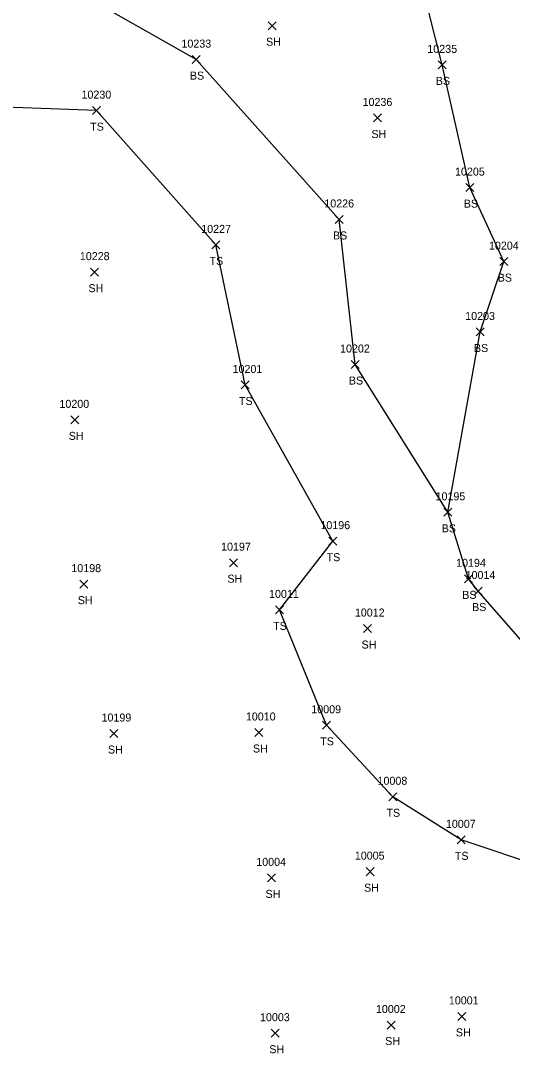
# Model space of a CAD drawing. Extents: x 1475671 to 1477951, y 592661 to 593821.
# Drawn here: x 1476720.5 to 1476843.4, y 592698.9 to 592957 of the extents above; entities that cross this region are included whole.
import ezdxf

# ---------------------------------------------------------------- set-up
doc = ezdxf.new("R2010")
doc.units = 0
for name, color, linetype in [('L_A', 7, 'Continuous'), ('L_I', 7, 'Continuous'), ('L_TIC', 7, 'Continuous'), ('LELB', 7, 'Continuous')]:
    doc.layers.add(name, color=color, linetype=linetype)

msp = doc.modelspace()

# ---------------------------------------------------------------- linework, layer by layer
at = {"layer": 'L_TIC'}
for points in [[(1476782.31, 592954.69), (1476784.31, 592956.69)], [(1476784.31, 592954.69), (1476782.31, 592956.69)], [(1476763.33, 592946.22), (1476765.33, 592948.22)], [(1476765.33, 592946.22), (1476763.33, 592948.22)], [(1476824.78, 592944.91), (1476826.78, 592946.91)], [(1476826.78, 592944.91), (1476824.78, 592946.91)], [(1476738.44, 592933.48), (1476740.44, 592935.48)], [(1476740.44, 592933.48), (1476738.44, 592935.48)], [(1476808.65, 592931.64), (1476810.65, 592933.64)], [(1476810.65, 592931.64), (1476808.65, 592933.64)], [(1476831.77, 592914.24), (1476833.77, 592916.24)], [(1476833.77, 592914.24), (1476831.77, 592916.24)], [(1476799.09, 592906.29), (1476801.09, 592908.29)], [(1476801.09, 592906.29), (1476799.09, 592908.29)], [(1476768.27, 592899.93), (1476770.27, 592901.93)], [(1476770.27, 592899.93), (1476768.27, 592901.93)], [(1476840.26, 592895.75), (1476842.26, 592897.75)], [(1476842.26, 592895.75), (1476840.26, 592897.75)], [(1476737.94, 592893.12), (1476739.94, 592895.12)], [(1476739.94, 592893.12), (1476737.94, 592895.12)], [(1476834.32, 592878.17), (1476836.32, 592880.17)], [(1476836.32, 592878.17), (1476834.32, 592880.17)], [(1476803.05, 592870.04), (1476805.05, 592872.04)], [(1476805.05, 592870.04), (1476803.05, 592872.04)], [(1476775.62, 592864.94), (1476777.62, 592866.94)], [(1476777.62, 592864.94), (1476775.62, 592866.94)], [(1476733, 592856.22), (1476735, 592858.22)], [(1476735, 592856.22), (1476733, 592858.22)], [(1476826.26, 592833.12), (1476828.26, 592835.12)], [(1476828.26, 592833.12), (1476826.26, 592835.12)], [(1476826.26, 592833.12), (1476828.26, 592835.12)], [(1476828.26, 592833.12), (1476826.26, 592835.12)], [(1476797.53, 592825.91), (1476799.53, 592827.91)], [(1476799.53, 592825.91), (1476797.53, 592827.91)], [(1476772.67, 592820.53), (1476774.67, 592822.53)], [(1476774.67, 592820.53), (1476772.67, 592822.53)], [(1476735.25, 592815.17), (1476737.25, 592817.17)], [(1476737.25, 592815.17), (1476735.25, 592817.17)], [(1476831.4, 592816.5), (1476833.4, 592818.5)], [(1476833.4, 592816.5), (1476831.4, 592818.5)], [(1476833.85, 592813.45), (1476835.85, 592815.45)], [(1476835.85, 592813.45), (1476833.85, 592815.45)], [(1476784.16, 592808.74), (1476786.16, 592810.74)], [(1476786.16, 592808.74), (1476784.16, 592810.74)], [(1476806.18, 592804.08), (1476808.18, 592806.08)], [(1476808.18, 592804.08), (1476806.18, 592806.08)], [(1476779.03, 592778.11), (1476781.03, 592780.11)], [(1476781.03, 592778.11), (1476779.03, 592780.11)], [(1476795.94, 592779.91), (1476797.94, 592781.91)], [(1476797.94, 592779.91), (1476795.94, 592781.91)], [(1476742.8, 592777.85), (1476744.8, 592779.85)], [(1476744.8, 592777.85), (1476742.8, 592779.85)], [(1476812.49, 592762.05), (1476814.49, 592764.05)], [(1476814.49, 592762.05), (1476812.49, 592764.05)], [(1476829.58, 592751.29), (1476831.58, 592753.29)], [(1476831.58, 592751.29), (1476829.58, 592753.29)], [(1476806.82, 592743.34), (1476808.82, 592745.34)], [(1476808.82, 592743.34), (1476806.82, 592745.34)], [(1476782.19, 592741.79), (1476784.19, 592743.79)], [(1476784.19, 592741.79), (1476782.19, 592743.79)], [(1476829.75, 592707.18), (1476831.75, 592709.18)], [(1476831.75, 592707.18), (1476829.75, 592709.18)], [(1476812.09, 592705.02), (1476814.09, 592707.02)], [(1476814.09, 592705.02), (1476812.09, 592707.02)], [(1476783.12, 592702.98), (1476785.12, 592704.98)], [(1476785.12, 592702.98), (1476783.12, 592704.98)]]:
    msp.add_lwpolyline(points, dxfattribs=at)
at = {"layer": 'LELB'}
for points in [[(1476827.26, 592834.12), (1476835.32, 592879.17), (1476841.26, 592896.75), (1476832.77, 592915.24), (1476825.78, 592945.91), (1476820.93, 592965.41), (1476796.57, 592984.14), (1476754.48, 593009.66), (1476722.03, 593058.18)], [(1476850.04, 592796.99), (1476834.85, 592814.45), (1476832.4, 592817.5), (1476827.26, 592834.12), (1476804.05, 592871.04), (1476800.09, 592907.29), (1476764.33, 592947.22), (1476734.93, 592963.95), (1476717.53, 592992.71), (1476686.74, 592992.91), (1476656.64, 592987.69)], [(1476851.45, 592745.32), (1476830.58, 592752.29), (1476813.49, 592763.05), (1476796.94, 592780.91), (1476785.16, 592809.74), (1476798.53, 592826.91), (1476776.62, 592865.94), (1476769.27, 592900.93), (1476739.44, 592934.48), (1476707.14, 592935.66), (1476679.51, 592942.26), (1476659.28, 592944.64), (1476643.97, 592910.56)]]:
    msp.add_lwpolyline(points, dxfattribs=at)

# ---------------------------------------------------------------- texts
at = {"layer": 'L_A'}
for s, p in [('SH', (1476781.8, 592950.69)), ('BS', (1476762.77, 592942.22)), ('BS', (1476824.22, 592940.91)), ('TS', (1476737.85, 592929.48)), ('SH', (1476808.14, 592927.64)), ('BS', (1476831.21, 592910.24)), ('BS', (1476798.53, 592902.29)), ('TS', (1476767.68, 592895.93)), ('BS', (1476839.7, 592891.75)), ('SH', (1476737.43, 592889.12)), ('BS', (1476833.76, 592874.17)), ('BS', (1476802.49, 592866.04)), ('TS', (1476775.03, 592860.94)), ('SH', (1476732.49, 592852.22)), ('BS', (1476825.7, 592829.12)), ('BS', (1476825.7, 592829.12)), ('TS', (1476796.94, 592821.91)), ('SH', (1476772.16, 592816.53)), ('BS', (1476830.84, 592812.5)), ('SH', (1476734.74, 592811.17)), ('BS', (1476833.29, 592809.45)), ('TS', (1476783.57, 592804.74)), ('SH', (1476805.67, 592800.08)), ('TS', (1476795.35, 592775.91)), ('SH', (1476742.29, 592773.85)), ('SH', (1476778.52, 592774.11)), ('TS', (1476811.89, 592758.05)), ('TS', (1476828.99, 592747.29)), ('SH', (1476781.68, 592737.79)), ('SH', (1476806.31, 592739.34)), ('SH', (1476811.58, 592701.02)), ('SH', (1476829.24, 592703.18)), ('SH', (1476782.61, 592698.98))]:
    msp.add_text(s, height=2, dxfattribs=at).set_placement(p)
at = {"layer": 'L_I'}
for s, p in [('10233', (1476760.66, 592950.22)), ('10235', (1476822.11, 592948.91)), ('10230', (1476735.68, 592937.48)), ('10236', (1476805.93, 592935.64)), ('10205', (1476829.03, 592918.24)), ('10226', (1476796.37, 592910.29)), ('10227', (1476765.6, 592903.93)), ('10204', (1476837.51, 592899.75)), ('10228', (1476735.27, 592897.12)), ('10203', (1476831.57, 592882.17)), ('10202', (1476800.3, 592874.04)), ('10201', (1476773.44, 592868.94)), ('10200', (1476730.17, 592860.22)), ('10195', (1476824.16, 592837.12)), ('10195', (1476824.16, 592837.12)), ('10196', (1476795.38, 592829.91)), ('10197', (1476770.57, 592824.53)), ('10194', (1476829.3, 592820.5)), ('10198', (1476733.14, 592819.17)), ('10014', (1476831.67, 592817.45)), ('10011', (1476782.55, 592812.74)), ('10012', (1476804, 592808.08)), ('10009', (1476793.11, 592783.91)), ('10199', (1476740.69, 592781.85)), ('10010', (1476776.76, 592782.11)), ('10008', (1476809.66, 592766.05)), ('10007', (1476826.75, 592755.29)), ('10005', (1476803.99, 592747.34)), ('10004', (1476779.36, 592745.79)), ('10001', (1476827.49, 592711.18)), ('10002', (1476809.26, 592709.02)), ('10003', (1476780.29, 592706.98))]:
    msp.add_text(s, height=2, dxfattribs=at).set_placement(p)

doc.saveas('drawing.dxf')
